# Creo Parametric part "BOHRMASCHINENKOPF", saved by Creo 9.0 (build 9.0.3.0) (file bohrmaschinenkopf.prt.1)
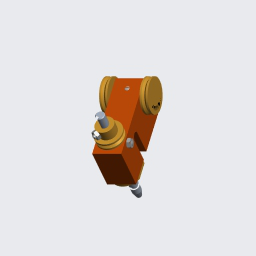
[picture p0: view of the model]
Units: millimeter Kilogram Sec (mmKs); MM, KILOGRAM, SECS
Materials in the file: S235JRG2

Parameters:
  COPY_GEOM_ORIGIN_TYPE = "Part"
  BENENNUNG = "XXX"
  DATUM = "XX.XX.XX"
  ERSTELLER = "ARINDA"
  TEILETYP = "Fertigungsteil"
  PTC_MASTER_MATERIAL = "S235JRG2"
  SELECT_EN_NAME = "S235JRG2"
  SELECT_DIN_NAME = "RSt37-2"
  SELECT_DIN_NUMBER = "1.0038"
  SELECT_ASTM_NAME = "A 283 M Grade 2"
  MATERIAL_GROUP = "ME_ST_Baustahl"
  STANDARD_EN_DELIVERYSPEC = "DIN EN 10025"
  STANDARD_DIN_DELIVERYSPEC = "DIN 17100"

Other parameters: MASSE

Created from: ARINDA-STARTTEIL.PRT

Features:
  1. coordinate system "CS0"
  2. datum plane "DTM1", "T_RECHTS_Y-Z"
  3. datum plane "DTM2", "T_OBEN_X-Z"
  4. datum plane "DTM3", "T_VORNE_X-Y"
  5. datum axis "T_X-ACHSE"
  6. datum axis "A_1"
  7. datum axis "A_2"
  8. feature "Externe Kopiegeom ID 40"
  9. feature "Externe Kopiegeom ID 103"
  10. feature "Externe Kopiegeom ID 115"
  11. feature "Externe Kopiegeom ID 127"
  12. feature "Externe Kopiegeom ID 278"
  13. feature "Externe Kopiegeom ID 429"
  14. feature "Externe Kopiegeom ID 452"
  15. feature "Externe Kopiegeom ID 494"
  16. feature "Externe Kopiegeom ID 509"
  17. feature "Externe Kopiegeom ID 552"
  18. feature "Externe Kopiegeom ID 633"
  19. feature "Externe Kopiegeom ID 664"

Other named items: T_BASIC, T_Y-ACHSE, T_Z-ACHSE

Layers: 00_STD-ACHSEN, 00_STD-EBENEN, 00_STD-KOORDSYS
